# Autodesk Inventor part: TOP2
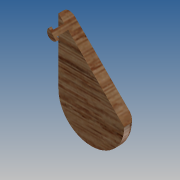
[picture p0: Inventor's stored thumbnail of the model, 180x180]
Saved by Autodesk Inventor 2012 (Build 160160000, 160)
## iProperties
Created: 2011-01
Part Number: TOP2
Document SubType Name: Modeling
Designer: Microsoft
Density: 1 g/cm^3
Material: Default
Author: Microsoft
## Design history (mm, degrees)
sketch "Sketch1"
  geometry: L1 (9.525, 0)-(9.525, 19.05); L2 (-9.525, 19.05)-(-9.525, 0); L3 (-9.525, 19.05)-(9.525, 0); A1 r 9.525 centre (0, 0) between (-9.525, 0) and (9.525, 0); A2 r 9.525 centre (0, 19.05) between (9.525, 19.05) and (-9.525, 19.05); 1 further point
  constraints: 6 end point, 4 point on circle, 3 tangent, 2 centre point, 1 coincident, 1 vertical alignment
  dimensions: "d3" = 9.525 radius of A2; "d4" = 9.525 radius of A1; "d5" = 19.05 distance of L1.start L1.end; "d6" = 19.05 distance of point (0, 0) A2.centre
extrude "Extrusion1" new body sketch "Sketch1" distance "d7" = 19.05; taper "d8" = 0 deg
sketch "Sketch2"
  geometry: L1 (13.47, 0)-(13.47, 19.05) reference; C1 r 0.794 at (13.47, 9.525); 1 further point
  constraints: 1 centre point, 1 midpoint
  dimensions: "d9" = 1.5875 diameter of C1
extrude "Extrusion2" cut sketch "Sketch2" distance "d10" = 6.35; taper "d11" = 0 deg
sketch "Sketch3"
  geometry: C1 r 0.794 at (0, 0) reference; C2 r 1.587 at (0, 0); 1 further point
  constraints: 1 centre point, 1 coincident
  dimensions: "d12" = 3.175 diameter of C2
extrude "Extrusion3" cut sketch "Sketch3" distance "d13" = 0.79375; taper "d14" = 0 deg
workplane "Work Plane1"
sketch "Sketch4"
  geometry: L1 (9.525, 19.05)-(-9.525, 0) reference; L2 (9.525, 0)-(9.525, 19.05) reference; L3 (9.525, 19.05)-(5.927, 22.648); L4 (9.525, 19.05)-(-9.525, 0) reference; C1 r 0.794 at (7.28, 16.805); A1 r 9.525 centre (0, 0) between (-9.525, 0) and (9.525, 0) reference; 1 further point
  constraints: 2 end point, 1 centre point, 1 perpendicular, 1 point on line
  dimensions: "d16" = 1.5875 diameter of C1; "d17" = 3.175 distance from line of L3 C1.centre
extrude "Extrusion4" cut sketch "Sketch4" distance "d18" = 6.35; taper "d19" = 0 deg
sketch "Sketch5"
  geometry: L1 (6.719, 16.244)-(7.841, 17.366) reference; C1 r 1.587 at (7.28, 16.805); A1 r 0.794 centre (7.28, 16.805) between (6.719, 16.244) and (7.841, 17.366) reference; 1 further point
  constraints: 1 centre point, 1 coincident
  dimensions: "d20" = 3.175 diameter of C1
extrude "Extrusion5" cut sketch "Sketch5" distance "d21" = 3.175; taper "d22" = 0 deg
sketch "Sketch6"
  geometry: L1 (-9.525, 0)-(9.525, 19.05) reference; L2 (9.525, 19.05)-(9.525, 0) reference; A1 r 9.525 centre (0, 0) between (-9.525, 0) and (9.525, 0) reference
extrude "Extrusion6" sketch "Sketch6" distance "d23" = 3.175; taper "d24" = 0 deg
fillet "Fillet1" dims "d36" = 2.54
sketch "Sketch10"
  geometry: L1 (9.525, 0)-(-9.525, 19.05); L2 (-9.525, 19.05)-(-6.03, 22.545); A1 r 0.794 centre (-7.28, 16.805) between (-7.841, 17.366) and (-6.719, 16.244)
  constraints: 4 end point, 3 point on line, 2 point on circle, 1 centre point, 1 perpendicular
  dimensions: "d37" = 1.5875 diameter of A1; "d38" = 3.175 distance from line of A1.centre L2
extrude "Extrusion10" join sketch "Sketch10" distance "d39" = 3.175; taper "d40" = 0 deg
sketch "Sketch11"
  geometry: L1 (-7.841, 17.366)-(-6.719, 16.244); L2 (9.525, 0)-(-9.525, 19.05); L3 (-6.157, 15.682)-(-8.402, 17.927); A1 r 0.794 centre (-7.28, 16.805) between (-7.841, 17.366) and (-6.719, 16.244); A2 r 1.587 centre (-7.28, 16.805) between (-8.402, 17.927) and (-6.157, 15.682); 2 further points
  constraints: 6 end point, 4 point on circle, 2 centre point, 2 point on line, 1 coincident
  dimensions: "d41" = 3.175 diameter of A2
extrude "Extrusion11" join sketch "Sketch11" distance "d42" = 0.79375; taper "d43" = 0 deg
sketch "Sketch12"
  geometry: L1 (9.525, 0)-(-6.719, 16.244) reference; L2 (-6.985, 0)-(-9.525, 0) reference; L3 (-7.938, 0)-(-7.937, 15.36); A1 r 9.525 centre (0, 0) between (-9.525, 0) and (9.525, 0) reference; A2 r 1.587 centre (-7.28, 16.805) between (-8.402, 17.927) and (-6.157, 15.682) reference; A3 r 7.938 centre (0, 0) between (-7.938, 0) and (7.732, 1.793)
  constraints: 3 point on circle, 2 end point, 2 point on line, 1 centre point, 1 coincident, 1 perpendicular, 1 tangent
  dimensions: "d44" = 15.875 diameter of A3
extrude "Extrusion12" cut sketch "Sketch12" distance "d45" = 0.79375; taper "d46" = 0 deg
body "Solid1"
node "Projected Loop1"
other parameters: "d15" = -6.35
